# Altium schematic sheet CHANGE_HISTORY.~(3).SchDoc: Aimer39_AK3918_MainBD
size 431 x 279 mm; Revision: 1.2.1; Release Date: 2014-05-28; SchModifyDate: 2020.11.1; PCBVersion: V1.0.0; PCBPartNumber: EVB_PHY_SZ18201; 版本号: V1.0.0
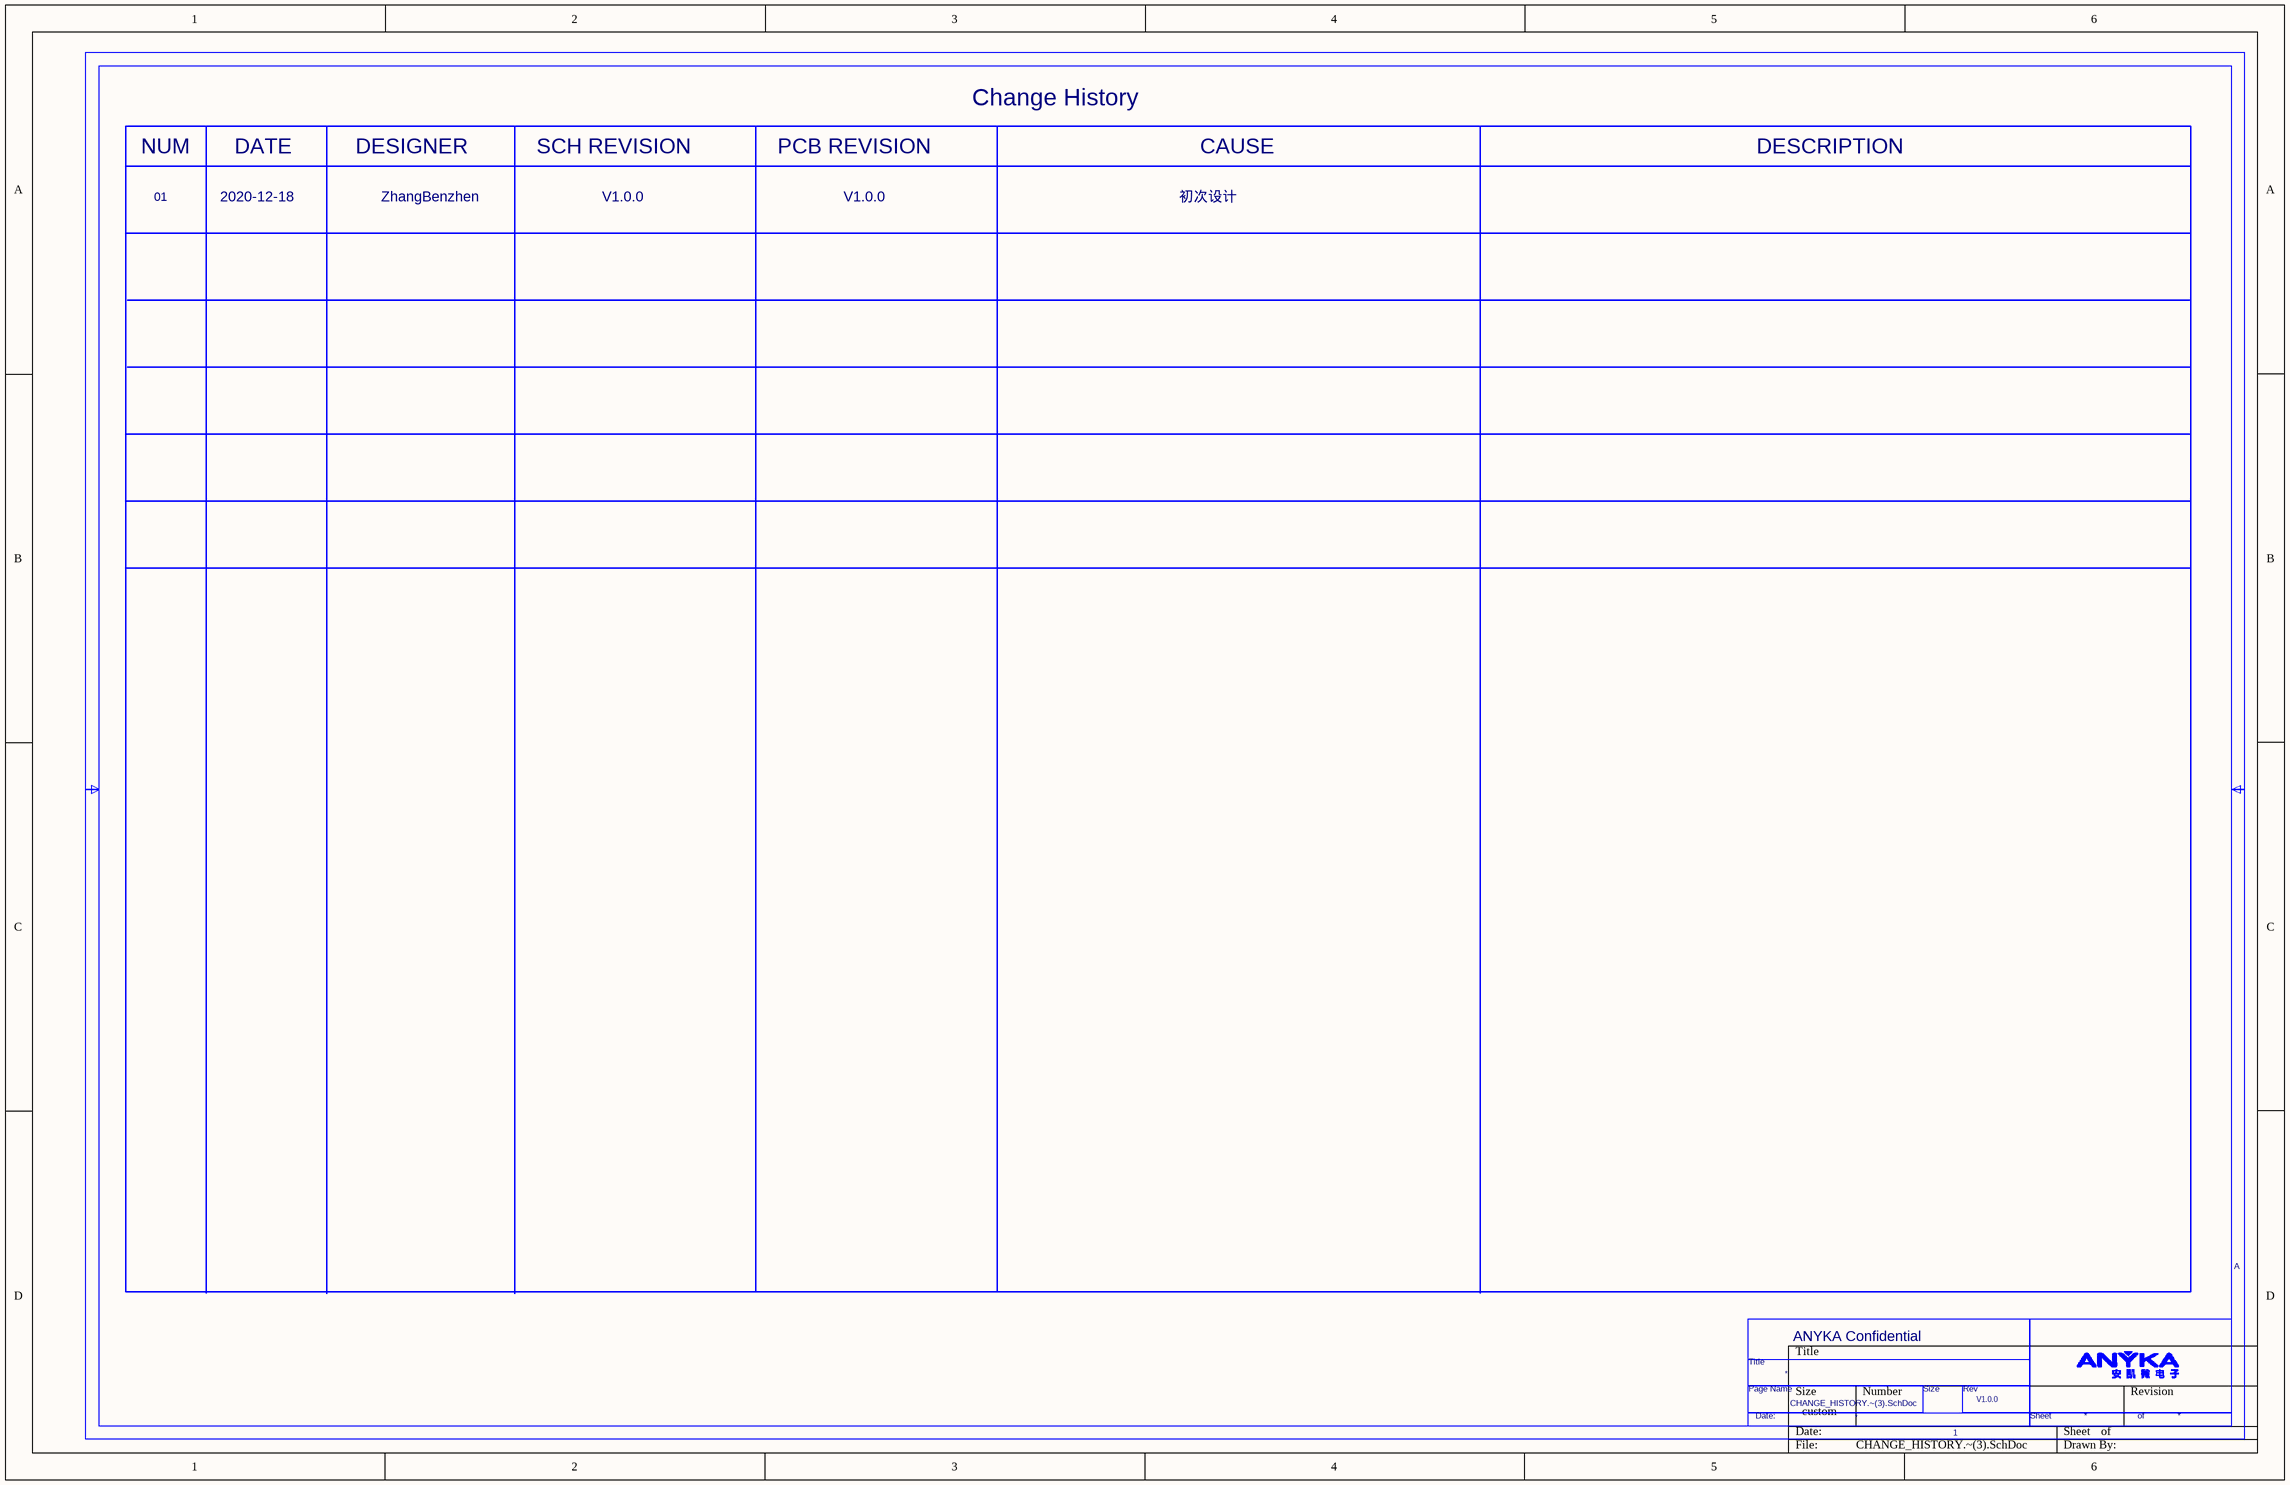
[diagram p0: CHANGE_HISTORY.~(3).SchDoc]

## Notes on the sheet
- NUM
- DATE
- DESIGNER
- SCH REVISION
- PCB REVISION
- Change History
- CAUSE
- DESCRIPTION
- 01
- 2020-12-18
- ZhangBenzhen
- V1.0.0
- 初次设计
- A
- Title
- ANYKA Confidential
- Page Name
- Date:
- Size
- 1
- Rev
- Sheet
- of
